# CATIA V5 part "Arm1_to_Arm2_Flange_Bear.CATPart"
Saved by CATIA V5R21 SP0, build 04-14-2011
Part number: Arm1_to_Arm2_Flange_Bear
Bounding box of the stored display mesh (mm): x -7.8 to 7.8, y -7.8 to 7.8, z 0 to 4
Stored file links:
  F:\教程\Robotic_Arm_Arduino_Kinect\机械臂CAD\Arm_Detailed_Design\Arm1_to_Arm2_Flange_Bear.CATPart
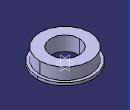
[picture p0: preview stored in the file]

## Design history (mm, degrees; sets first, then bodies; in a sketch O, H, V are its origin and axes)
Body1 (main body)
  Sketch1 on xy-plane, origin (0, 0, 0), H (1, 0, 0), V (0, 1, 0)
    circle A1 centre (0, 0) radius 7.8
    radius A1 = 7.8
  Pad1: profile Sketch1, direction (0, 0, 1), length 0.78
  Sketch2 on end face of Pad1, origin (0, 0, 0.78), H (1, 0, 0), V (0, 1, 0)
    circle A1 centre (0, 0) radius 7
    radius A1 = 7
  Pad2: profile Sketch2, direction (0, 0, 1), length 3.22
  Sketch3 on end face of Pad2, origin (0, 0, 4), H (1, 0, 0), V (0, 1, 0)
    circle A1 centre (0, 0) radius 4
    radius A1 = 4
  Pocket1: profile Sketch3, direction (0, 0, -1), through (limit type 3)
